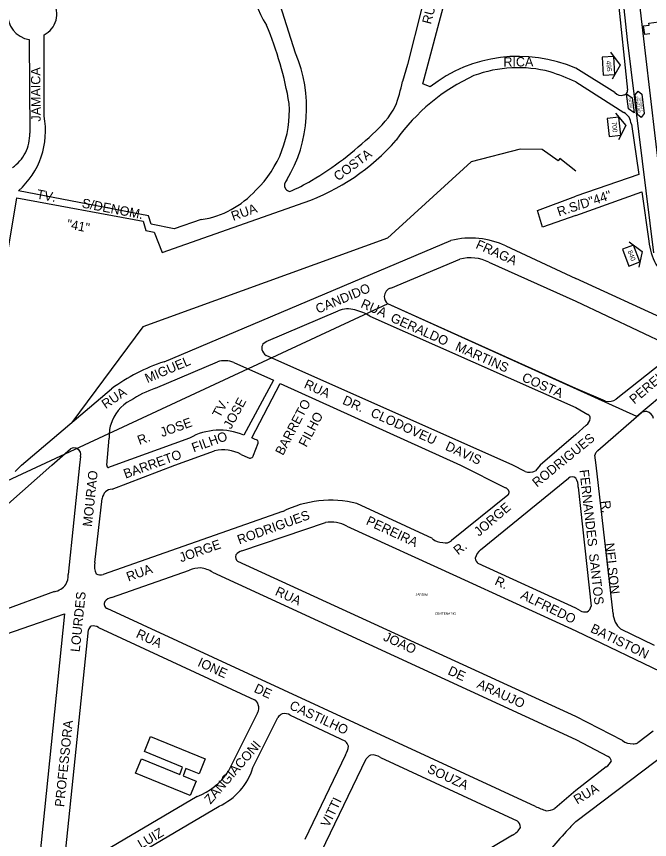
# Model space of a CAD drawing. Extents: x 325709 to 364434, y 7573432 to 7597073.
# Drawn here: x 338123 to 338529, y 7587762 to 7588289 of the extents above; entities that cross this region are included whole.
import ezdxf

# ---------------------------------------------------------------- set-up
doc = ezdxf.new("R2010")
doc.units = 0
for name, color, linetype in [('EDIFEXISTENT', 7, 'Continuous'), ('EDIFOBRAEXIS', 7, 'Continuous'), ('FORMATO', 7, 'Continuous'), ('LIMITE_BAIRROS_MUNICIPIOS', 7, 'Continuous'), ('LOGRADOURO', 7, 'Continuous'), ('LOGRADOURO_TEXTO', 7, 'Continuous'), ('NUM_REF', 7, 'Continuous'), ('SIMBOLO', 7, 'Continuous'), ('TEXTO', 7, 'Continuous'), ('TUBO_PEAD_GN_125', 7, 'Continuous')]:
    doc.layers.add(name, color=color, linetype=linetype)

# ---------------------------------------------------------------- blocks, each defined once
blk = doc.blocks.new('NUM_REF')
at = {"layer": 'NUM_REF'}
blk.add_lwpolyline([(-4.3125, 0.9375), (0, 3.75), (4.3125, 0.9375)], dxfattribs=at)
blk.add_lwpolyline([(2.875, -1.875), (2.875, 1.875), (-2.875, 1.875), (-2.875, -1.875)], close=True, dxfattribs=at)

msp = doc.modelspace()

# ---------------------------------------------------------------- linework, layer by layer
at = {"layer": 'EDIFEXISTENT'}
for p, q in [((338524.88, 7588283.19), (338528.34, 7588283.61)), ((338525.53, 7588277.79), (338524.88, 7588283.19)), ((338528.18, 7588284.93), (338534.52, 7588285.69)), ((338528.34, 7588283.61), (338528.18, 7588284.93)), ((338528.9, 7588278.19), (338525.53, 7588277.79)), ((338205.07, 7587818.35), (338209.08, 7587828.1)), ((338209.08, 7587828.1), (338244.06, 7587813.85)), ((338229.57, 7587808.37), (338205.07, 7587818.35)), ((338199.38, 7587804.47), (338203.16, 7587813.75)), ((338203.16, 7587813.75), (338227.69, 7587803.76)), ((338244.06, 7587813.85), (338240.08, 7587804.1)), ((338227.69, 7587803.76), (338229.57, 7587808.37)), ((338231.72, 7587807.51), (338229.82, 7587802.85)), ((338240.08, 7587804.1), (338231.72, 7587807.51)), ((338234.5, 7587790.16), (338199.38, 7587804.47)), ((338229.82, 7587802.85), (338238.27, 7587799.41)), ((338238.27, 7587799.41), (338234.5, 7587790.16))]:
    msp.add_line(p, q, dxfattribs=at)
at = {"layer": 'EDIFOBRAEXIS'}
msp.add_lwpolyline([(338481.39, 7588190.13), (338471.26, 7588198.35), (338470.08, 7588196.82), (338459.91, 7588204.12), (338445.71, 7588204.19), (338414.48, 7588196.06), (338360.86, 7588147.14), (338204.04, 7588090.5), (338158.53, 7588029.1)], dxfattribs=at)
at = {"layer": 'LIMITE_BAIRROS_MUNICIPIOS'}
msp.add_line((338360.99, 7588105.23), (337766.16, 7587828.43), dxfattribs=at)
msp.add_lwpolyline([(338658.06, 7588094.03), (338634.08, 7588085.05), (338616.69, 7588132.14), (338538.57, 7588122.47), (338542.82, 7588051.83), (338520.53, 7588032.92), (338360.99, 7588105.23)], dxfattribs=at)
at = {"layer": 'LOGRADOURO'}
for p, q in [((338500.3, 7588379.98), (338514.51, 7588242.01)), ((338383.5, 7588246.03), (338407.29, 7588336.25)), ((338301.92, 7588265.72), (338288.55, 7588307.63)), ((338140.81, 7588225.45), (338140.9, 7588277.47)), ((338131.28, 7588274.4), (338131.77, 7588214.51)), ((338506.48, 7588240.44), (338481.39, 7588256.07)), ((338388.05, 7588244.16), (338383.5, 7588246.03)), ((338481.39, 7588247.3), (338512.24, 7588227.62)), ((338517, 7588220.26), (338521.7, 7588187.93)), ((338521.7, 7588187.93), (338481.39, 7588174.07)), ((338481.39, 7588161.75), (338523.8, 7588176.86)), ((338523.8, 7588176.86), (338528.13, 7588145.38)), ((338114.84, 7588121.58), (338123.37, 7588173.14)), ((338481.39, 7588161.75), (338460.13, 7588154.37)), ((338217.7, 7588068.1), (338401.44, 7588145.71)), ((338436.61, 7588142.26), (338481.39, 7588121.31)), ((338362.92, 7588115.3), (338407.21, 7588133.76)), ((338425.81, 7588131.81), (338481.39, 7588106.81)), ((338557.19, 7588086.62), (338481.39, 7588121.31)), ((338481.39, 7588051.05), (338360.99, 7588105.23)), ((338481.39, 7588106.81), (338547.18, 7588075.85)), ((338349.58, 7588097.23), (338481.39, 7588038.68)), ((338441.12, 7588001.91), (338283.05, 7588072.12)), ((338547.18, 7588075.85), (338507.36, 7588044.2)), ((338212.18, 7588051.12), (338251.87, 7588068.12)), ((338262.39, 7588067.61), (338287.71, 7588056.23)), ((338287.71, 7588056.23), (338268.68, 7588021.11)), ((338126.4, 7588001.91), (338184.08, 7588050.81)), ((338273.84, 7588019.37), (338292.06, 7588054.13)), ((338292.06, 7588054.13), (338407.49, 7588001.91)), ((338500.42, 7588042.94), (338481.39, 7588051.05)), ((338481.39, 7588038.68), (338489.03, 7588034.27)), ((338495.47, 7588011.22), (338523.55, 7588035.52)), ((338488.09, 7588027.39), (338481.39, 7588021.46)), ((338180.98, 7588001.91), (338182.55, 7588019.13)), ((338234.01, 7588019.21), (338186.12, 7588001.91)), ((338276.13, 7588018.36), (338273.84, 7588019.37)), ((338481.39, 7588021.46), (338458.6, 7588001.91)), ((338274.88, 7588008.25), (338277.86, 7588015.85)), ((338145.75, 7588001.91), (338157.7, 7588012.37)), ((338164.16, 7588007.48), (338163.61, 7588001.91)), ((338224.65, 7588001.91), (338250.06, 7588011.04)), ((338267.01, 7588008.61), (338271.38, 7588006.72)), ((338494.48, 7588001.91), (338493.61, 7588008.22)), ((338117.71, 7587976.84), (338145.75, 7588001.91)), ((338126.4, 7588001.91), (338122.28, 7587997.74)), ((338163.61, 7588001.91), (338156.22, 7587931.71)), ((338186.12, 7588001.91), (338182.1, 7588000.3)), ((338184.41, 7587986.55), (338224.65, 7588001.91)), ((338407.49, 7588001.91), (338436.31, 7587987.4)), ((338448.91, 7587997.84), (338441.12, 7588001.91)), ((338458.6, 7588001.91), (338455.5, 7587998.27)), ((338505.27, 7587906.84), (338494.48, 7588001.91)), ((338420.38, 7587947.54), (338476.73, 7587993.53)), ((338483, 7587987.79), (338491.18, 7587911.58)), ((338437.95, 7587982.57), (338401.79, 7587953.68)), ((338173.42, 7587939.43), (338178.06, 7587980.58)), ((338389.62, 7587954.77), (338341.16, 7587977.29)), ((338293.46, 7587972.06), (338178.71, 7587931.71)), ((338267.54, 7587946.95), (338321.01, 7587965.02)), ((338334.68, 7587962.67), (338404.99, 7587930.85)), ((338481.39, 7587840.79), (338264.95, 7587940.13)), ((338183.99, 7587917.07), (338234.01, 7587934.63)), ((338481.39, 7587910.34), (338418.96, 7587938.79)), ((338248.71, 7587933.25), (338481.39, 7587826.14)), ((338404.99, 7587930.85), (338481.39, 7587895.74)), ((338147.43, 7587920.82), (338112.7, 7587908.21)), ((338455.6, 7587783.26), (338181.32, 7587910.05)), ((338484.35, 7587908.59), (338481.39, 7587910.34)), ((338116.36, 7587893.7), (338153.87, 7587906.69)), ((338153.87, 7587906.69), (338122.95, 7587604.82)), ((338175.64, 7587897.94), (338275.65, 7587851.61)), ((338531.75, 7587886.29), (338510.24, 7587896.81)), ((338153.39, 7587743.78), (338169.31, 7587896.36)), ((338481.39, 7587895.74), (338549.47, 7587862.88)), ((338277.52, 7587843.22), (338258.57, 7587805.29)), ((338274.63, 7587808.16), (338290.45, 7587840.14)), ((338298.48, 7587841.63), (338333.81, 7587824.96)), ((338511.35, 7587825.44), (338481.39, 7587840.79)), ((338530.95, 7587831.57), (338521.05, 7587823.9)), ((338481.39, 7587826.14), (338502.08, 7587815.23)), ((338481.39, 7587773.64), (338545.14, 7587821.79)), ((338333.95, 7587816.39), (338307.85, 7587762.06)), ((338318.61, 7587754.35), (338347.19, 7587813.68)), ((338356.26, 7587814.56), (338443.76, 7587774.01)), ((338500.93, 7587808.56), (338481.39, 7587793.56)), ((338481.39, 7587793.56), (338467.95, 7587781.87)), ((338238.95, 7587789.66), (338156.59, 7587741.2)), ((338161.82, 7587729.88), (338252.89, 7587783.45)), ((338440.79, 7587764.88), (338289.14, 7587674.46))]:
    msp.add_line(p, q, dxfattribs=at)
for points in [[(338538.96, 7588156.51), (338526.15, 7588265.77), (338517.56, 7588339.38), (338513.14, 7588380.63), (338511.45, 7588396.78), (338509.44, 7588411.92), (338506.66, 7588428.27), (338503.31, 7588444.16), (338499.69, 7588459.51)], [(338393.17, 7588334.42), (338390.86, 7588324.03), (338382.89, 7588294.72), (338373.54, 7588258.43), (338370.44, 7588247.55)], [(338209.39, 7588156.25), (338207.65, 7588161.5), (338124.48, 7588177.64)], [(338123.37, 7588173.14), (338204.23, 7588158.09), (338206.02, 7588152.25), (338211.41, 7588151.15)], [(338460.13, 7588154.37), (338456.96, 7588164.93), (338481.39, 7588174.07)], [(338211.41, 7588151.15), (338216.36, 7588137.97), (338307.36, 7588170.1)], [(338241.54, 7588159.11), (338224.08, 7588153.31), (338209.39, 7588156.25)], [(338281.03, 7588079.64), (338283.06, 7588081.14), (338329.22, 7588100.72)]]:
    msp.add_lwpolyline(points, dxfattribs=at)
for centre, radius, start, end in [((338319.62, 7588309.34), 44.43, 136.2076, 215.3359), ((338133.91, 7588290.67), 16.48, 90.2764, 260.8287), ((338133.88, 7588290.87), 15.13, 297.6682, 31.3353), ((338065.69, 7588193.78), 235.5, 9.6932, 22.4323), ((338218.63, 7588230.62), 90.38, 329.3363, 22.8521), ((338444.75, 7588171.52), 92.14, 66.5651, 127.9727), ((338444.48, 7588174.96), 81.46, 75.4663, 110.3251), ((338469, 7588136.9), 126.06, 114.7728, 144.5573), ((338398.93, 7588063.04), 201.88, 65.8903, 70.9192), ((338257.3, 7588271.91), 115.73, 339.6354, 347.8477), ((338510.35, 7588243.68), 5.05, 219.9256, 290.548), ((338511.8, 7588241.66), 2.73, 276.6396, 7.347), ((338226.54, 7588228.97), 71.43, 314.3901, 3.5769), ((338311.84, 7588261.23), 61.55, 309.7404, 331.2638), ((338090.92, 7588215.8), 50.82, 311.3284, 10.951), ((338506.05, 7588217.18), 12.14, 38.4141, 59.3145), ((338496.94, 7588216.21), 20.47, 11.4396, 24.5822), ((338102.47, 7588214.51), 29.29, 334.4656, 359.9987), ((338201.07, 7588370.52), 216.94, 300.801, 313.7863), ((338261.92, 7588300.72), 138.3, 289.1816, 319.0079), ((338102.83, 7588216.48), 29.88, 306.437, 330.7618), ((338299.28, 7588181.1), 4.49, 130.1937, 210.9596), ((338256.34, 7588277.43), 108.68, 292.7242, 300.9002), ((338232.23, 7588218.3), 59.91, 278.9411, 317.6446), ((338298.86, 7588181.6), 4.44, 219.3304, 263.059), ((338414.2, 7588094.81), 52.47, 64.7188, 104.0682), ((338568.02, 7588149.73), 40.13, 186.224, 230.5069), ((338414, 7588108.79), 25.87, 62.8543, 105.2234), ((338364.72, 7588109.48), 6.09, 107.1869, 176.4577), ((338364.71, 7588110.03), 6.07, 181.6855, 232.1895), ((338335.38, 7588085.11), 16.78, 74.1319, 111.5245), ((338333.53, 7588072.35), 29.61, 57.1767, 77.439), ((338285.88, 7588076.91), 5.56, 150.6936, 189.4468), ((338285.88, 7588076.91), 5.56, 189.4468, 239.4357), ((338256.17, 7587951.98), 122.33, 108.3301, 126.1097), ((338256.35, 7588051.95), 16.78, 68.9272, 105.5075), ((338233.87, 7587987.1), 67.59, 108.7167, 123.9282), ((338207.66, 7588020.87), 25.12, 117.3108, 163.9319), ((338502.5, 7588051.2), 8.52, 255.8383, 304.7561), ((338488.42, 7588032.09), 2.27, 349.2856, 74.3401), ((338526.22, 7588030.69), 5.52, 83.3286, 119.0018), ((338525.7, 7588030.66), 5.64, 10.3111, 78.1255), ((338483.89, 7588032.8), 6.85, 307.7708, 350.4233), ((338207.05, 7588020.77), 24.55, 163.3236, 183.845), ((338253.28, 7587984.99), 39.27, 66.9046, 119.3765), ((338276.1, 7588016.48), 1.88, 340.1868, 89.0234), ((338159.75, 7588008.49), 4.39, 57.0814, 117.9261), ((338160.57, 7588008.72), 3.79, 340.9201, 65.5698), ((338255.58, 7587989.2), 22.53, 59.5149, 104.1787), ((338272.65, 7588008.58), 2.26, 235.7899, 351.4496), ((338495.62, 7588008.19), 2.01, 138.7388, 179.1568), ((338499.61, 7588006.53), 6.26, 131.4526, 151.5334), ((338182.16, 7588001.53), 1.23, 162.0809, 267.3926), ((338451.69, 7588005.91), 8.53, 250.9555, 296.5023), ((338479.07, 7587990.83), 3.57, 49.3595, 130.8801), ((338473.59, 7587988.25), 9.42, 357.212, 34.1101), ((338184.96, 7587979.61), 6.97, 94.5358, 171.9618), ((338434.86, 7587983.61), 4.05, 21.8706, 69.0313), ((338435.4, 7587984.6), 3.27, 321.4362, 9.1354), ((338324.39, 7587910.15), 69.2, 75.9774, 116.5438), ((338324.94, 7587946.98), 18.46, 58.183, 102.3004), ((338395.98, 7587961.72), 9.43, 227.5584, 270.9643), ((338397.89, 7587957.41), 5.4, 251.1518, 316.3416), ((338266.82, 7587942.97), 3.41, 155.5593, 236.6003), ((338270.14, 7587938.95), 8.41, 108.0244, 139.7994), ((338426.18, 7587940.12), 9.42, 127.9948, 166.4154), ((338183.95, 7587936.98), 10.82, 166.9074, 206.1741), ((338421.21, 7587942.32), 4.18, 179.7363, 237.5237), ((338241.11, 7587917.11), 18.91, 90.1854, 112.0684), ((338239.34, 7587919.3), 16.81, 56.0939, 84.1477), ((338146.07, 7587930.8), 10.2, 328.0244, 5.1485), ((338177.07, 7587937.3), 5.82, 240.9575, 286.3451), ((338144.98, 7587932.81), 12.24, 281.5496, 322.7299), ((338182.38, 7587912.85), 3, 147.8483, 249.2904), ((338185.15, 7587910.63), 6.55, 100.2524, 144.278), ((338487.6, 7587915.33), 7.49, 244.2544, 277.8911), ((338486.75, 7587911.95), 4.44, 295.0076, 355.2051), ((338519.01, 7587907.41), 13.75, 182.3446, 230.3929), ((338172.78, 7587895.52), 3.57, 119.867, 166.4562), ((338172.65, 7587893.64), 5.24, 55.1841, 108.2988), ((338273.41, 7587847.45), 4.73, 11.575, 61.7083), ((338272.15, 7587846.37), 6.23, 329.6685, 19.0366), ((338299.15, 7587832.73), 11.43, 120.764, 139.6128), ((338294.85, 7587836.23), 6.51, 56.0543, 103.6542), ((338328, 7587818.91), 8.38, 20.645, 46.1325), ((338517.43, 7587833.61), 10.19, 233.3728, 273.981), ((338518.69, 7587829.54), 6.11, 264.8105, 292.7203), ((338321.05, 7587823.9), 14.93, 329.7935, 352.179), ((338353.03, 7587810.06), 6.87, 116.6188, 148.145), ((338350.98, 7587807.17), 9.09, 54.4666, 96.5416), ((338496.3, 7587815.8), 8.6, 302.6197, 337.3209), ((338500.09, 7587811.46), 4.26, 13.8156, 62.136), ((338236.56, 7587819.73), 39.79, 294.2274, 343.0967), ((338224.46, 7587827.99), 40.98, 290.7101, 326.3518), ((338501.91, 7587886.99), 113.6, 245.9415, 249.7148), ((338460.29, 7587799.89), 19.57, 276.5633, 293.0344), ((338441.35, 7587770.11), 4.58, 356.6275, 58.3247), ((338748.91, 7587514.84), 372.22, 135.9489, 137.3321), ((338436.2, 7587774.77), 10.9, 294.8666, 333.1082), ((338745.93, 7587517.65), 368.12, 137.3398, 142.2322)]:
    msp.add_arc(centre, radius, start, end, dxfattribs=at)
at = {"layer": 'SIMBOLO'}
for points in [[(338517.6, 7588237.09), (338518.85, 7588227.56), (338515.11, 7588230.09), (338513.86, 7588239.62)], [(338520.91, 7588226.48), (338519.45, 7588239.02), (338521.37, 7588241.45), (338521.37, 7588241.45), (338523.8, 7588239.53), (338525.26, 7588226.99), (338523.34, 7588224.56), (338523.34, 7588224.56)]]:
    msp.add_lwpolyline(points, close=True, dxfattribs=at)
at = {"layer": 'TUBO_PEAD_GN_125'}
msp.add_lwpolyline([(338471.19, 7588725.25), (338488.24, 7588459.31), (338503.32, 7588376.71), (338514.33, 7588274.23), (338531.15, 7588137.78)], dxfattribs=at)

# ---------------------------------------------------------------- block references
at = {"layer": 'FORMATO'}
for p, xscale, yscale, rotation in [((338502.38, 7588257.56), 1.9999999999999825, 1.9999999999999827, -86.36333078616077), ((338505.96, 7588218.56), 1.9999999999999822, 1.9999999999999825, -83.55404847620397), ((338516.9, 7588136.09), 1.9999999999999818, 1.9999999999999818, -69.13104796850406)]:
    msp.add_blockref('NUM_REF', p, dxfattribs=dict(at, xscale=xscale, yscale=yscale, rotation=rotation))

# ---------------------------------------------------------------- texts
for s, rotation, p in [('495', 273.6367, (338500.97, 7588260.8)), ('700', 276.446, (338504.39, 7588221.72)), ('840', 290.869, (338514.59, 7588138.77))]:
    msp.add_text(s, height=3, rotation=rotation).set_placement(p)
at = {"layer": 'LIMITE_BAIRROS_MUNICIPIOS'}
for s, p in [('JARDIM', (338378.83, 7587918.2)), ('CENTENARIO', (338391.1, 7587906.03))]:
    msp.add_text(s, height=1.5, dxfattribs=at).set_placement(p)
at = {"layer": 'LOGRADOURO_TEXTO'}
for s, rotation, p in [('RUA', 75.5575, (338388.65, 7588283.9)), ('RICA', 0.4748, (338435.06, 7588257.12)), ('JAMAICA', 90.4613, (338138.65, 7588221.91)), ('COSTA', 36.4504, (338329.12, 7588183.54)), ('TV.', 349.0758, (338135.67, 7588172.68)), ('R.S/D"44"', 18.1937, (338470.58, 7588161.07)), ('S/DENOM.', 349.0758, (338164.72, 7588166.89)), ('RUA', 19.4432, (338261.94, 7588158.26)), (' "41"', 349.0758, (338152.81, 7588153.98)), ('FRAGA', 335.779, (338416.83, 7588141.04)), ('CANDIDO', 22.6267, (338316.25, 7588098.79)), ('RUA', 336.0496, (338343.18, 7588103.14)), ('GERALDO', 336.0496, (338362.22, 7588094.04)), ('MARTINS', 336.0496, (338403.71, 7588075.73)), ('MIGUEL', 22.9844, (338206.96, 7588054.38)), ('PEREIRA', 40.6127, (338518.88, 7588040.66)), ('COSTA', 336.0496, (338446.36, 7588055.97)), ('RUA', 335.8074, (338306.84, 7588051.59)), ('RUA', 34.1776, (338180.26, 7588037.68)), ('JOSE', 61.5514, (338260.58, 7588024.5)), ('DR.', 335.6583, (338331.51, 7588041.29)), ('TV.', 61.5514, (338253.45, 7588031.73)), ('BARRETO', 62.3454, (338293.85, 7588007.65)), ('FILHO', 62.3454, (338308.84, 7588012.97)), ('CLODOVEU', 335.6583, (338349.47, 7588033.32)), ('JOSE', 19.8568, (338216.48, 7588019.76)), ('R.', 19.8568, (338201.9, 7588014.71)), ('FILHO', 19.8568, (338236.66, 7588009.99)), ('RODRIGUES', 39.2882, (338456.53, 7587987.41)), ('DAVIS', 335.6583, (338397.34, 7588011.85)), ('BARRETO', 19.8568, (338193.01, 7587993.17)), ('MOURAO', 83.9919, (338171.47, 7587962.2)), ('FERNANDES', 276.4726, (338483.73, 7587998.69)), ('JORGE', 40.6127, (338419.38, 7587955.95)), ('R.', 276.4726, (338497.49, 7587978.87)), ('RODRIGUES', 19.8865, (338265.87, 7587951)), ('PEREIRA', 335.0764, (338346.57, 7587964.1)), ('JORGE', 19.3698, (338228.57, 7587939.58)), ('R.', 38.5451, (338406.04, 7587944.02)), ('NELSON', 276.4726, (338499.97, 7587951.71)), ('SANTOS', 276.4726, (338489.79, 7587944.92)), ('RUA', 19.9495, (338194.85, 7587927.27)), ('R.', 335.5026, (338429.01, 7587925.57)), ('RUA', 335.3471, (338288.33, 7587918.9)), ('LOURDES', 84.1504, (338163.6, 7587881.96)), ('ALFREDO', 333.9019, (338445.53, 7587916.74)), ('RUA', 335.1924, (338199.22, 7587891.76)), ('BATISTON', 333.9019, (338490.3, 7587895.22)), ('JOAO', 335.3471, (338357.58, 7587889.85)), ('IONE', 335.1924, (338238.7, 7587873.46)), ('DE', 335.3471, (338398.97, 7587868.06)), ('DE', 335.1924, (338274.82, 7587856.76)), ('ARAUJO', 335.3471, (338417.48, 7587859.56)), ('CASTILHO', 335.1924, (338297.46, 7587845.89)), ('PROFESSORA', 84.1504, (338153.61, 7587782.71)), ('ZANGIACONI', 49.1771, (338247.45, 7587784.35)), ('SOUZA', 335.1924, (338385.75, 7587805.26)), ('RUA', 30.699, (338482.26, 7587784.47)), ('VITTI', 64.3344, (338323.17, 7587769.48)), ('LUIZ', 30.464, (338203.03, 7587755.97))]:
    msp.add_text(s, height=6, rotation=rotation, dxfattribs=at).set_placement(p)
at = {"layer": 'TEXTO'}
for s, rotation, p in [('200,00', 97.4869, (338517.58, 7588230.49)), ('DN 125mm', 96.6509, (338522.72, 7588227.72)), ('7 Kgf/cm²', 97.1631, (338524.43, 7588228.55))]:
    msp.add_text(s, height=1.5, rotation=rotation, dxfattribs=at).set_placement(p)

doc.saveas('drawing.dxf')
